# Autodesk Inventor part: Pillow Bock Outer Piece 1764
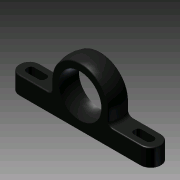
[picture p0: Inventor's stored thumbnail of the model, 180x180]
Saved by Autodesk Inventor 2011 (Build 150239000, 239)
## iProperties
Created: 2009-01
Part Number: Pillow Bock Outer Piece 1764
Document SubType Name: Modeling
Designer: lwoods
Density: 1.4 g/cm^3
Material: PVC-Piping
Mass: 16.083 g
Surface Area: 61.8162 cm^2
Volume: 11.4879 cm^3
Author: lwoods
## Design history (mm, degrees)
sketch "Sketch1"
  geometry: L1 (106.919, -24.218)-(106.919, -34.759); L2 (106.919, -34.759)-(21.575, -34.759); L3 (21.575, -34.759)-(21.575, -24.218); L4 (55.774, -29.552)-(75.813, -29.552); L5 (64.247, -16.738)-(64.247, -29.552); L6 (21.575, -24.218)-(53.842, -24.218); L7 (74.651, -24.218)-(106.919, -24.218); L8 (46.276, -16.738)-(46.276, -24.218); L9 (82.217, -16.738)-(82.217, -24.218); L10 (64.247, 1.233)-(64.247, -34.759); A1 r 12.814 centre (64.247, -16.738) between (64.247, -3.924) and (74.651, -24.218); A2 r 17.971 centre (64.247, -16.738) between (64.247, 1.233) and (82.217, -16.738)
  constraints: 20 end point, 7 point on circle, 6 perpendicular, 3 parallel, 3 point on line, 2 centre point, 2 horizontal, 2 tangent, 1 coincident, 1 midpoint
  dimensions: "d0" = 10.541 distance of L1.start L1.end; "d1" = 85.344 distance of L1.end L2.end; "d2" = 42.672 distance from line of L1 L5.start; "d3" = 5.207 distance between parallel lines of L2 L4; "d4" = 0 distance from line of L4 L5.end; "d5" = 12.8143 distance of L5.start L5.end; "d6" = 35.941 diameter of A2
extrude "Extrusion2" new body sketch "Sketch1" stored distance "d12" = 12.192; taper "d13" = 0 deg
revolve "Revolution1" stored, may be unused: angle "d14" = 90 deg
sketch "Sketch2"
  geometry: L1 (0, 0)-(85.344, 0); L2 (85.344, 0)-(85.344, -12.192); L3 (85.344, -12.192)-(0, -12.192); L4 (0, -12.192)-(0, 0); L5 (0, 0)-(87.475, 0); L6 (87.475, 0)-(87.475, 19.156); L7 (87.475, 19.156)-(0, 19.156); L8 (0, 19.156)-(0, 0); L9 (0, -12.192)-(88.547, -12.192); L10 (88.547, -12.192)-(88.547, -30.812); L11 (88.547, -30.812)-(0, -30.812); L12 (0, -30.812)-(0, -12.192)
  constraints: 24 end point, 6 parallel, 3 horizontal, 3 perpendicular
extrude "Extrusion3" cut sketch "Sketch2" distance "d15" = 127; taper "d16" = 0 deg
sketch "Sketch3"
  geometry: L1 (55.815, -24.218)-(53.842, -24.218) reference; L2 (74.651, -24.218)-(72.678, -24.218) reference; C1 r 12.814 at (64.247, -16.738); A1 r 12.814 centre (64.247, -16.738) between (53.842, -24.218) and (74.651, -24.218) reference; A2 r 11.271 centre (64.247, -16.738) between (72.678, -24.218) and (55.815, -24.218) reference; A3 r 16.905 centre (64.247, -16.738) between (81.152, -16.738) and (47.342, -16.738) reference
  constraints: 1 centre point, 1 coincident, 1 concentric
extrude "Extrusion4" cut sketch "Sketch3" distance "d17" = 127; taper "d18" = 0 deg
fillet "Fillet4" dims "d19" = 2.54
fillet "Fillet5" dims "d20" = 6.096
sketch "Sketch4"
  geometry: L1 (-36.576, -6.096)-(-19.584, -6.096) reference; L2 (-19.584, 6.096)-(-36.576, 6.096) reference; L3 (-37.353, 2.451)-(-27.493, 2.451); L4 (-27.493, 2.451)-(-27.493, -2.451); L5 (-27.493, -2.451)-(-37.353, -2.451); L6 (-37.353, -2.451)-(-37.353, 2.451); L7 (-37.353, 0)-(-38.227, 0); L8 (-38.227, 0)-(-42.672, 0); L9 (-27.493, 0)-(-26.619, 0); L10 (-16.905, -6.096)-(16.905, -6.096) reference; L11 (16.905, 6.096)-(-16.905, 6.096) reference; L12 (0, 6.096)-(0, -6.096); L13 (37.353, 2.451)-(27.493, 2.451); L14 (27.493, -2.451)-(37.353, -2.451); C1 r 3.175 at (-31.191, 0); C2 r 3.175 at (31.191, 0); A1 r 6.096 centre (-36.576, 0) between (-36.576, 6.096) and (-36.576, -6.096) reference; A2 r 20.51 centre (0, 0) between (-19.584, 6.096) and (-19.584, -6.096) reference; A3 r 3.873 centre (-34.354, 0) between (-37.353, 2.451) and (-37.353, -2.451); A4 r 6.096 centre (-36.576, 0) between (-36.576, 6.096) and (-36.576, -6.096) reference; A5 r 3.873 centre (-30.493, 0) between (-27.493, -2.451) and (-27.493, 2.451); A6 r 17.97 centre (0, 0) between (16.905, -6.096) and (16.905, 6.096) reference; A7 r 17.97 centre (0, 0) between (-16.905, 6.096) and (-16.905, -6.096) reference; A8 r 3.873 centre (30.493, 0) between (27.493, 2.451) and (27.493, -2.451); A9 r 3.873 centre (34.353, 0) between (37.353, -2.451) and (37.353, 2.451)
  constraints: 20 end point, 11 point on circle, 7 symmetric about line, 6 centre point, 4 midpoint, 2 parallel, 2 tangent, 1 equal radius, 1 horizontal, 1 perpendicular, 3 other
  dimensions: "d21" = 4.9022 distance of L3.end L4.end; "d22" = 3.6449 distance between parallel lines of L2 L3; "d23" = 4.445 distance of L7.end L8.end; "d24" = 11.6078 distance of L9.end L7.end; "d36" = 6.35 diameter of C1
extrude "Extrusion5" cut sketch "Sketch4" distance "d25" = 127; taper "d26" = 0 deg
fillet "Fillet6" dims "d27" = 2.032
fillet "Fillet7" dims "d28" = 0.635
workplane "Work Plane1"
  workaxis "Work Axis1"
sketch "Sketch5"
  geometry: L1 (-5.661, 0)-(-5.661, 0) reference; L2 (-5.661, 0)-(5.661, 0) reference; L3 (5.661, 0)-(5.661, 0) reference; L4 (5.661, 0)-(-5.661, 0) reference; L5 (-9.563, 10.935)-(9.563, 10.935); L6 (9.563, 10.935)-(9.563, 7.938); L7 (9.563, 7.938)-(-9.563, 7.938); L8 (-9.563, 7.938)-(-9.563, 10.935); L9 (0, 10.935)-(0, 14.11); L10 (-6.096, 8.115)-(6.096, 8.115) reference; L11 (-6.096, 8.115)-(-6.096, 18.021) reference; L12 (-6.096, 18.021)-(6.096, 18.021) reference; L13 (6.096, 18.021)-(6.096, 8.115) reference; L14 (0, 18.021)-(0, 17.186); L15 (-13.388, 0)-(13.388, 0) reference; A1 r 15.99 centre (0, -1.88) between (9.563, 10.935) and (-9.563, 10.935)
  constraints: 12 end point, 3 parallel, 3 point on circle, 2 midpoint, 1 centre point, 1 horizontal, 1 perpendicular
  dimensions: "d30" = 3.175 distance of L9.start L9.end; "d31" = 2.9972 distance of L7.end L5.start; "d32" = 19.1262 distance of L6.end L7.end; "d33" = 7.9375 distance between parallel lines of L7 L2; "d34" = 0 distance between parallel lines of L14 L9
revolve "Revolution2" sketch "Sketch5" stored, may be unused: angle "d35" = 90 deg
body "Solid1"
node "Projected Loop1"
node "Projected Loop2"
node "Projected Loop3"
node "Projected Loop4"
other parameters: "d29" = 90 deg
